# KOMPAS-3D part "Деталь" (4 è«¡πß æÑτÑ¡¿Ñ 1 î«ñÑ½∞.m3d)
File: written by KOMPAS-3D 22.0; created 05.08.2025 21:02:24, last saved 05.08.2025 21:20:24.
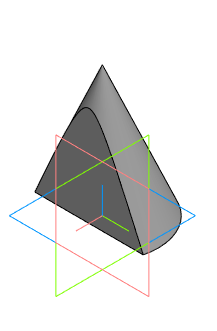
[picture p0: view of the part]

Document properties: Автор: user; Полное имя файла: G:\08 05 вторник\2025 НГ Лаб работы\Лаб 4 Сечение конуса\4 Модели\4 Конус Сечение 3 Модель.m3d

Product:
- Part/product: Деталь
    Масса: 0.373939

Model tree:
1. Эскиз:1
2. Элемент вращения:1
     Угол 1 = 360
3. Эскиз:2  (with: Элемент вращения:1)
4. Элемент выдавливания:1
     Расстояние 1 = 30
